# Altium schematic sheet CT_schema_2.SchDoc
size 313 x 185 mm
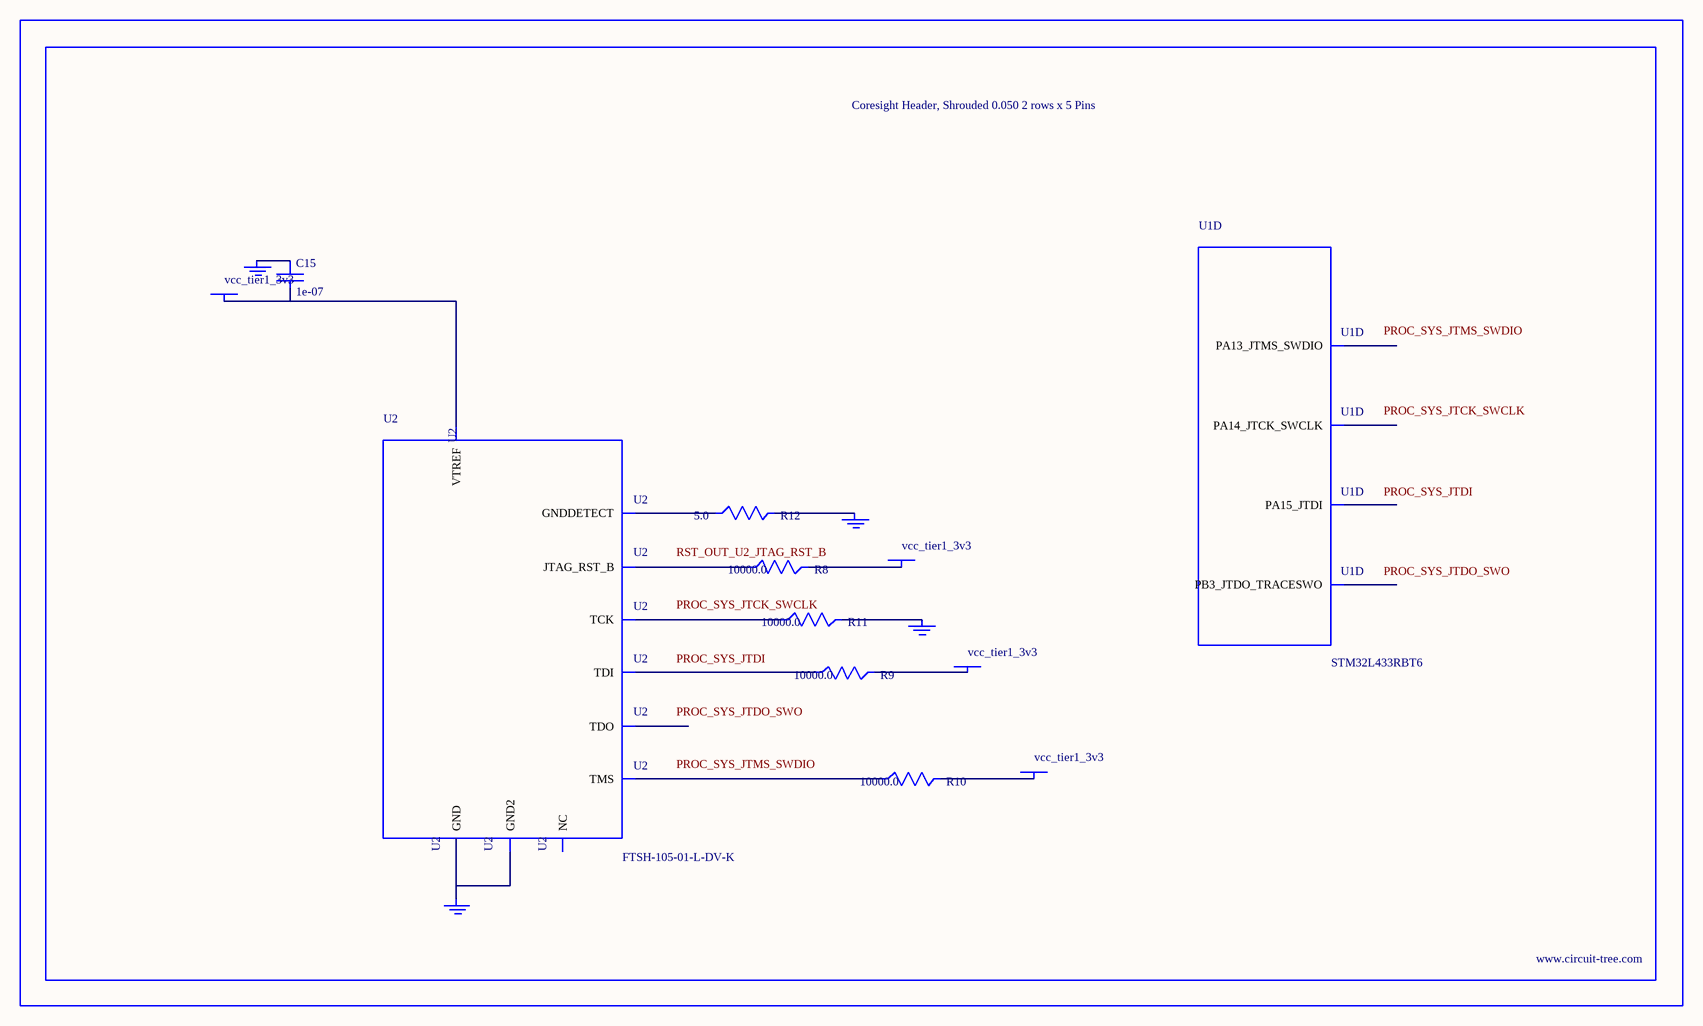
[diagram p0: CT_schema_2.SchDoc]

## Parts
BORDER1  (no value)
C15  1e-07  [C0402]
GND_INSTANCE_1_0  (no value)
GND_INSTANCE_1_1  (no value)
GND_INSTANCE_1_2  (no value)
GND_INSTANCE_1_3  (no value)
POWER_INSTANCE_1_0  vcc_tier1_3v3
POWER_INSTANCE_1_1  vcc_tier1_3v3
POWER_INSTANCE_1_2  vcc_tier1_3v3
POWER_INSTANCE_1_3  vcc_tier1_3v3
R8  10000.0  [R0603]
R9  10000.0  [R0603]
R10  10000.0  [R0603]
R11  10000.0  [R0603]
R12  5.0  [R0603]
U1  STM32L433RBT6  [LQFP64]  (part D of 7)
U2  FTSH-105-01-L-DV-K  [SAMTEC_FTSH-105-01-L-DV-K]

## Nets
NetC15_1: C15.1 GND_INSTANCE_1_0.0(GND)
NetC15_2: C15.2 POWER_INSTANCE_1_0.0(PWR) U2.1(VTREF)
NetGND_INSTANCE_1_1_0: GND_INSTANCE_1_1.0(GND) R11.2
NetGND_INSTANCE_1_2_0: GND_INSTANCE_1_2.0(GND) R12.2
NetGND_INSTANCE_1_3_0: GND_INSTANCE_1_3.0(GND) U2.3(GND) U2.5(GND2)
NetPOWER_INSTANCE_1_1_0: POWER_INSTANCE_1_1.0(PWR) R10.2
NetPOWER_INSTANCE_1_2_0: POWER_INSTANCE_1_2.0(PWR) R9.2
NetPOWER_INSTANCE_1_3_0: POWER_INSTANCE_1_3.0(PWR) R8.2
NetR8_1: R8.1 U2.10(JTAG_RST_B)
NetR9_1: R9.1 U2.8(TDI)
NetR10_1: R10.1 U2.2(TMS)
NetR11_1: R11.1 U2.4(TCK)
NetR12_1: R12.1 U2.9(GNDDETECT)

Not connected (* = marked no-connect by the designer): U1 46(PA13_JTMS_SWDIO) 49(PA14_JTCK_SWCLK) 50(PA15_JTDI) 55(PB3_JTDO_TRACESWO); U2 6(TDO) 7(NC)

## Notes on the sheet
- Labels drawn without touching a wire or pin: PROC_SYS_JTCK_SWCLK, PROC_SYS_JTDI, PROC_SYS_JTDO_SWO, PROC_SYS_JTMS_SWDIO, RST_OUT_U2_JTAG_RST_B

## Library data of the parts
BORDER1 = BORDER_PAGE1
C15 = C0402C104K3RACTU
GND_INSTANCE_1_0-GND_INSTANCE_1_3 = GND
POWER_INSTANCE_1_0-POWER_INSTANCE_1_3 = PWR
R8-R11 = RC0603JR-0710KL
R12 = ERJ-3GEYJ5R1V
